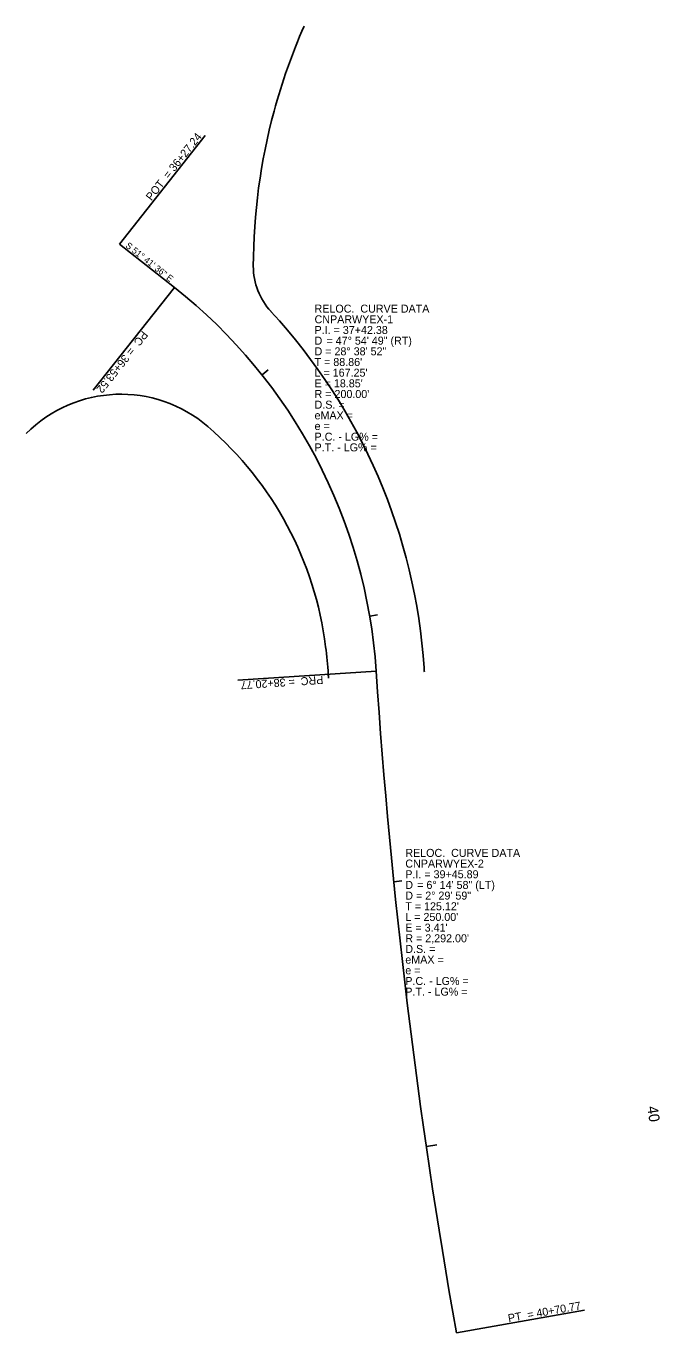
# Model space of a CAD drawing. Extents: x 2007405 to 2007642, y 1137080 to 1137569.
import ezdxf

# ---------------------------------------------------------------- set-up
doc = ezdxf.new("R2010")
doc.units = 0
for name, color, linetype in [('RD_HC_CL_Rel', 7, 'Continuous'), ('RD_HC_Data_Rel', 7, 'Continuous'), ('RD_HC_Data_Tic_Rel', 7, 'Continuous'), ('RD_HC_TX_Rel_Sta20', 7, 'Continuous'), ('RD_PD_Final_TrvlWay', 7, 'Continuous')]:
    doc.layers.add(name, color=color, linetype=linetype)

msp = doc.modelspace()

# ---------------------------------------------------------------- linework, layer by layer
at = {"layer": 'RD_HC_CL_Rel'}
msp.add_line((2007439.88, 1137487.72), (2007460.5, 1137471.43), dxfattribs=at)
for centre, radius, start, end in [((2007336.52, 1137314.49), 200, 3.7798, 51.6934), ((2009823.1, 1137478.77), 2292, 183.77984, 190.02938)]:
    msp.add_arc(centre, radius, start, end, dxfattribs=at)
at = {"layer": 'RD_HC_Data_Rel'}
for p, q in [((2007439.88, 1137487.72), (2007472, 1137528.38)), ((2007460.5, 1137471.43), (2007430.07, 1137432.91)), ((2007536.09, 1137327.67), (2007484.24, 1137324.25)), ((2007566.13, 1137079.61), (2007614.17, 1137088.1))]:
    msp.add_line(p, q, dxfattribs=at)
at = {"layer": 'RD_HC_Data_Tic_Rel'}
for p, q in [((2007493.31, 1137438.65), (2007495.67, 1137440.51)), ((2007533.65, 1137348.28), (2007536.6, 1137348.79)), ((2007542.68, 1137248.72), (2007545.66, 1137249.02)), ((2007554.88, 1137149.47), (2007558.84, 1137150.05))]:
    msp.add_line(p, q, dxfattribs=at)
at = {"layer": 'RD_PD_Final_TrvlWay'}
for centre, radius, start, end in [((2007715.05, 1137478.82), 225, 156.2645, 164.8789), ((2007715.05, 1137478.82), 225, 164.8789, 179.8483), ((2007515.05, 1137479.35), 25, 179.8483, 222.7212), ((2007336.52, 1137314.49), 218, 3.7798, 42.7212), ((2007440.4, 1137381.42), 50, 49.2104, 135.154), ((2007388.13, 1137320.85), 130, 7.0258, 49.2104), ((2007336.52, 1137314.49), 182, 3.7798, 7.0258), ((2009823.1, 1137478.77), 2310, 183.77984, 183.81818), ((2009823.1, 1137478.77), 2274, 183.77984, 183.81818)]:
    msp.add_arc(centre, radius, start, end, dxfattribs=at)

# ---------------------------------------------------------------- texts
at = {"layer": 'RD_HC_Data_Rel'}
for s, height, rotation, p in [('POT  = 36+27.24', 3, 51.6934, (2007451.88, 1137503.72)), ('S 51%%d 41\' 36" E', 2.4, 321.6934, (2007441.95, 1137486.72)), ('PC  = 36+53.52', 3, 231.6934, (2007448.49, 1137455.42)), ('PRC  = 38+20.77', 3, 183.7798, (2007516.17, 1137325.85)), ('PT  = 40+70.77', 3, 10.0294, (2007585.74, 1137083.58))]:
    msp.add_text(s, height=height, rotation=rotation, dxfattribs=at).set_placement(p)
for s, p in [('RELOC.  CURVE DATA', (2007513, 1137462)), ('CNPARWYEX-1', (2007513, 1137458)), ('P.I. = 37+42.38', (2007513, 1137454)), ('D', (2007513, 1137450)), ('    = 47%%d 54\' 49" (RT)', (2007513, 1137450)), ('D = 28%%d 38\' 52"', (2007513, 1137446)), ("T = 88.86'", (2007513, 1137442)), ("L = 167.25'", (2007513, 1137438)), ("E = 18.85'", (2007513, 1137434)), ("R = 200.00'", (2007513, 1137430)), ('D.S. = ', (2007513, 1137426)), ('eMAX = ', (2007513, 1137422)), ('e = ', (2007513, 1137418)), ('P.C. - LG% =', (2007513, 1137414)), ('P.T. - LG% =', (2007513, 1137410)), ('CNPARWYEX-2', (2007547, 1137254)), ('RELOC.  CURVE DATA', (2007547, 1137258)), ('P.I. = 39+45.89', (2007547, 1137250)), ('D', (2007547, 1137246)), ('    = 6%%d 14\' 58" (LT)', (2007547, 1137246)), ('D = 2%%d 29\' 59"', (2007547, 1137242)), ("T = 125.12'", (2007547, 1137238)), ("L = 250.00'", (2007547, 1137234)), ("E = 3.41'", (2007547, 1137230)), ("R = 2,292.00'", (2007547, 1137226)), ('D.S. = ', (2007547, 1137222)), ('eMAX = ', (2007547, 1137218)), ('e = ', (2007547, 1137214)), ('P.C. - LG% =', (2007547, 1137210)), ('P.T. - LG% =', (2007547, 1137206))]:
    msp.add_text(s, height=3, dxfattribs=at).set_placement(p)
at = {"layer": 'RD_HC_TX_Rel_Sta20'}
msp.add_text('40', height=4, rotation=278.2604, dxfattribs=at).set_placement((2007637.61, 1137164.32))

doc.saveas('drawing.dxf')
